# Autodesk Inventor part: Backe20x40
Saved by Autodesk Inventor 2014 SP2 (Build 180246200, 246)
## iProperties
Created: 2015-06
Part Number: Backe20x40
Material: Generisch
Document SubType Name: Modeling
Designer: e_krauts
Density: 1 g/cm^3
Appearance: Vorgabe
Author: e_krauts
Sending System: SolidWorks 2011
Last Author: e_boekem
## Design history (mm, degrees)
node "Backe20x40.ipt1"
node "Aufsatz-Linear austragen5"
node "Basis1"
